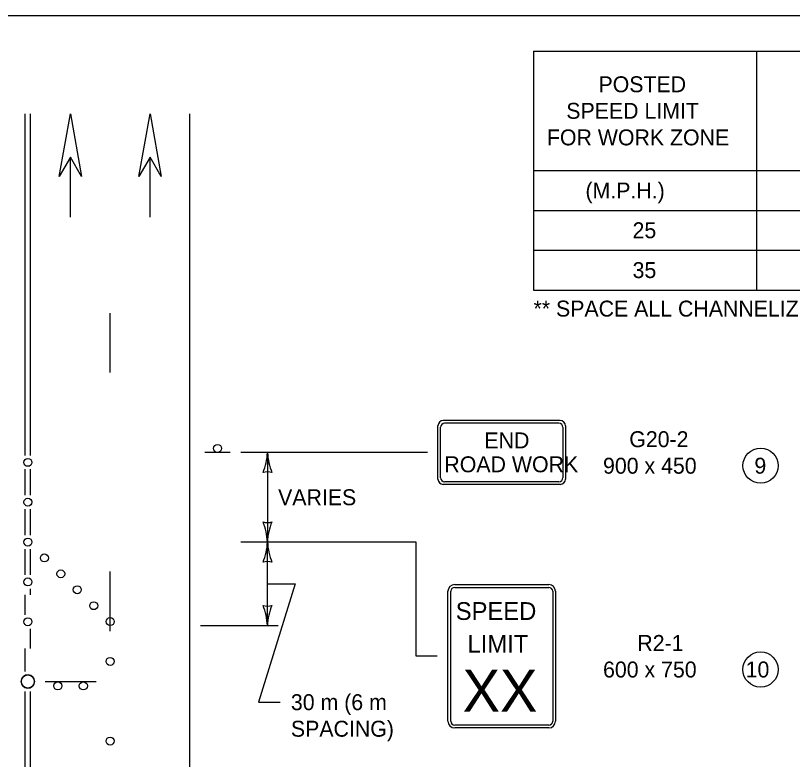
# Model space of a CAD drawing. Extents: x 49991.4 to 50021, y 49987.6 to 50011.4.
# Drawn here: x 50010.547 to 50013.473, y 49996.197 to 49998.999 of the extents above; entities that cross this region are included whole.
import ezdxf

# ---------------------------------------------------------------- set-up
doc = ezdxf.new("R2010")
doc.units = 0
for name, color, linetype in [('Level 1', 7, 'Continuous'), ('Level 2', 7, 'Continuous'), ('Level 3', 7, 'Continuous')]:
    doc.layers.add(name, color=color, linetype=linetype)

# ---------------------------------------------------------------- blocks, each defined once
blk = doc.blocks.new('ARR')
at = {"layer": 'Level 3'}
for centre, radius, start, end in [((1.53, 37.02), 37.05, 247.456, 267.6395), ((-21.37, 0), 9.13, 342.1388, 17.8612), ((1.92, -38.79), 38.83, 92.8273, 112.0772)]:
    blk.add_arc(centre, radius, start, end, dxfattribs=at)
blk = doc.blocks.new('G20-2')
at = {"layer": 'Level 1'}
for p, q in [((0.2197, 0.1196), (-0.2203, 0.1196)), ((-0.2403, -0.1004), (-0.2403, 0.0996)), ((-0.2303, -0.0954), (-0.2303, 0.0946)), ((0.2147, 0.1096), (-0.2153, 0.1096)), ((0.2297, 0.0946), (0.2297, -0.0954)), ((0.2397, 0.0996), (0.2397, -0.1004)), ((0.2147, -0.1104), (-0.2153, -0.1104)), ((0.2196, -0.1204), (-0.2204, -0.1204))]:
    blk.add_line(p, q, dxfattribs=at)
for centre, radius, start, end in [((-0.2203, 0.0996), 0.02, 90, 180), ((0.2197, 0.0996), 0.02, 360, 90), ((-0.2153, 0.0946), 0.015, 90, 180), ((0.2147, 0.0946), 0.015, 360, 90), ((-0.2204, -0.1004), 0.02, 180, 270), ((-0.2153, -0.0954), 0.015, 180, 270), ((0.2147, -0.0954), 0.015, 270, 360), ((0.2196, -0.1004), 0.02, 270, 360)]:
    blk.add_arc(centre, radius, start, end, dxfattribs=at)
for s, p in [('END', (-0.0655, 0.015)), ('ROAD WORK', (-0.2162, -0.075))]:
    blk.add_text(s, height=0.06, rotation=360, dxfattribs=at).set_placement(p)

msp = doc.modelspace()

# ---------------------------------------------------------------- linework, layer by layer
at = {"layer": 'Level 1'}
for p, q in [((50010.5832, 49997.3422), (50010.5832, 49998.6295)), ((50010.6032, 49997.3422), (50010.6032, 49998.6295)), ((50011.2032, 49993.9404), (50011.2032, 49998.6295)), ((50010.7532, 49998.2394), (50010.7532, 49998.4653)), ((50010.7536, 49998.2394), (50010.7536, 49998.4653)), ((50011.0532, 49998.2394), (50011.0532, 49998.4653)), ((50011.0536, 49998.2394), (50011.0536, 49998.4653)), ((50010.9033, 49997.6544), (50010.9033, 49997.8784)), ((50011.3556, 49997.3532), (50011.2596, 49997.3532)), ((50010.5832, 49997.1921), (50010.5832, 49997.2898)), ((50010.6032, 49997.1921), (50010.6032, 49997.2898)), ((50010.5832, 49997.0419), (50010.5832, 49997.1397)), ((50010.6032, 49997.0419), (50010.6032, 49997.1397)), ((50010.5832, 49996.8918), (50010.5832, 49996.9895)), ((50010.6032, 49996.8918), (50010.6032, 49996.9895)), ((50010.9033, 49996.6804), (50010.9033, 49996.9044)), ((50010.6032, 49996.8166), (50010.6032, 49996.8394)), ((50012.1753, 49996.3408), (50012.1753, 49996.8302)), ((50012.1858, 49996.3408), (50012.1858, 49996.8302)), ((50012.2006, 49996.8556), (50012.555, 49996.8556)), ((50012.2006, 49996.845), (50012.555, 49996.845)), ((50012.3778, 49996.8556), (50012.3778, 49996.8556)), ((50012.5698, 49996.8302), (50012.5698, 49996.3408)), ((50012.5803, 49996.8302), (50012.5803, 49996.3408)), ((50010.5832, 49996.7416), (50010.5832, 49996.8166)), ((50010.6032, 49996.6142), (50010.6032, 49996.6892)), ((50010.5832, 49996.5283), (50010.5832, 49996.6142)), ((50010.7541, 49996.4891), (50010.6581, 49996.4891)), ((50010.8501, 49996.4891), (50010.7541, 49996.4891)), ((50010.5832, 49995.5402), (50010.5832, 49996.4525)), ((50010.6032, 49995.5402), (50010.6032, 49996.4525)), ((50012.555, 49996.326), (50012.2006, 49996.326)), ((50012.555, 49996.3155), (50012.2006, 49996.3155))]:
    msp.add_line(p, q, dxfattribs=at)
for points in [[(49999.3835, 49998.9992), (50016.7501, 49998.9992), (50016.7501, 49987.7988), (49999.3835, 49987.7988)], [(50010.7116, 49998.393), (50010.7532, 49998.6295), (50010.7952, 49998.393), (50010.7532, 49998.4652)], [(50011.0116, 49998.393), (50011.0532, 49998.6295), (50011.0952, 49998.393), (50011.0532, 49998.4652)]]:
    msp.add_lwpolyline(points, close=True, dxfattribs=at)
for centre, radius in [((50011.3075, 49997.3684), 0.0152), ((50010.5932, 49997.316), 0.015), ((50010.5932, 49997.1659), 0.015), ((50010.5932, 49997.0157), 0.015), ((50010.6553, 49996.956), 0.015), ((50010.7173, 49996.896), 0.015), ((50010.5932, 49996.8656), 0.015), ((50010.7793, 49996.836), 0.015), ((50010.8413, 49996.776), 0.015), ((50010.5932, 49996.7154), 0.015), ((50010.9033, 49996.716), 0.015), ((50010.903, 49996.566), 0.015), ((50010.5932, 49996.4904), 0.025), ((50010.7061, 49996.4739), 0.0152), ((50010.8021, 49996.4739), 0.0152), ((50010.903, 49996.266), 0.015)]:
    msp.add_circle(centre, radius, dxfattribs=at)
for centre, radius, start, end in [((50012.2006, 49996.8302), 0.0253, 90, 180), ((50012.2006, 49996.8302), 0.0148, 90, 180), ((50012.555, 49996.8302), 0.0253, 0, 90), ((50012.555, 49996.8302), 0.0148, 0, 90), ((50010.5932, 49996.4904), 0.025, 357.0759, 177.0759), ((50010.5932, 49996.4904), 0.025, 177.0759, 357.0759), ((50012.2006, 49996.3408), 0.0253, 180, 270), ((50012.2006, 49996.3408), 0.0148, 180, 270), ((50012.555, 49996.3408), 0.0148, 270, 360), ((50012.555, 49996.3408), 0.0253, 270, 360)]:
    msp.add_arc(centre, radius, start, end, dxfattribs=at)
at = {"layer": 'Level 2'}
for p, q in [((50012.4976, 49998.8652), (50016.4276, 49998.8652)), ((50012.4976, 49998.8652), (50012.4976, 49997.9652)), ((50013.3376, 49998.8652), (50013.3376, 49997.9652)), ((50012.4976, 49998.4152), (50016.4276, 49998.4152)), ((50012.4976, 49998.2652), (50016.4276, 49998.2652)), ((50012.4976, 49998.1152), (50016.4276, 49998.1152)), ((50012.4976, 49997.9652), (50016.4276, 49997.9652))]:
    msp.add_line(p, q, dxfattribs=at)
for centre in [(50013.3526, 49997.3032), (50013.3525, 49996.5355)]:
    msp.add_circle(centre, 0.0662, dxfattribs=at)
at = {"layer": 'Level 3'}
for p, q in [((50012.0977, 49997.3532), (50011.3956, 49997.3532)), ((50011.4956, 49997.3532), (50011.4956, 49997.0157)), ((50012.0553, 49997.0157), (50011.3956, 49997.0157)), ((50011.4956, 49996.7011), (50011.4956, 49997.0157)), ((50011.6001, 49996.8584), (50011.4612, 49996.4124)), ((50011.4956, 49996.8584), (50011.6001, 49996.8584)), ((50011.2432, 49996.7011), (50011.5356, 49996.7011)), ((50011.4612, 49996.4124), (50011.5439, 49996.4124))]:
    msp.add_line(p, q, dxfattribs=at)
msp.add_lwpolyline([(50012.1353, 49996.5855), (50012.0553, 49996.5855), (50012.0553, 49997.0157)], dxfattribs=at)

# ---------------------------------------------------------------- block references
at = {"layer": 'Level 2', "xscale": 0.006, "yscale": 0.006}
for p, rotation in [((50011.4956, 49997.3532), 90), ((50011.4956, 49997.0157), -90), ((50011.4956, 49996.7011), -90)]:
    msp.add_blockref('ARR', p, dxfattribs=dict(at, rotation=rotation))
at = {"layer": 'Level 3', "xscale": 1.001, "yscale": 1.001}
msp.add_blockref('G20-2', (50012.3782, 49997.3536), dxfattribs=at)
at = {"layer": 'Level 3', "xscale": 0.006, "yscale": 0.006, "rotation": 90}
msp.add_blockref('ARR', (50011.4956, 49997.0157), dxfattribs=at)

# ---------------------------------------------------------------- texts
at = {"layer": 'Level 1'}
for s, height, p in [('SPEED', 0.06695, (50012.2047, 49996.7223)), ('LIMIT', 0.06695, (50012.249, 49996.5985)), ('XX', 0.15772, (50012.2307, 49996.3766))]:
    msp.add_text(s, height=height, dxfattribs=at).set_placement(p)
at = {"layer": 'Level 2'}
for s, height, p in [('POSTED', 0.06, (50012.7423, 49998.7102)), ('SPEED LIMIT', 0.06, (50012.621, 49998.6102)), ('FOR WORK ZONE', 0.06, (50012.5481, 49998.5102)), ('(M.P.H.)', 0.06, (50012.6932, 49998.3102)), ('25', 0.06, (50012.8706, 49998.1602)), ('35', 0.06, (50012.8707, 49998.0102)), ('** SPACE ALL CHANNELIZING DEVICES AT "G" UNLESS OTHERWISE NOTED.', 0.06, (50012.4976, 49997.8652)), ('G20-2', 0.06, (50012.8582, 49997.3732)), ('900 x 450', 0.06, (50012.7594, 49997.2732)), ('9', 0.0601, (50013.3294, 49997.2733)), ('VARIES', 0.06, (50011.5356, 49997.1545)), ('R2-1', 0.06, (50012.8886, 49996.6055)), ('600 x 750', 0.06, (50012.7594, 49996.5055)), ('10', 0.06006, (50013.2964, 49996.5056)), ('30 m (6 m', 0.06, (50011.5839, 49996.3824)), ('SPACING)', 0.06, (50011.5839, 49996.2824))]:
    msp.add_text(s, height=height, dxfattribs=at).set_placement(p)

doc.saveas('drawing.dxf')
